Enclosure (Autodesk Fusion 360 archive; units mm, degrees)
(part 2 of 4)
sketch "Sketch32" plane through (0, -174.4464, 63.4933) normal (0, -0.9397, 0.342) x axis (1, 0, 0)
  line L1 (50, 6.0998) -> (50, -13.9002)
  line L2 (-45, 11.0998) -> (45, 11.0998)
  line L3 (-50, -13.9002) -> (-50, 6.0998)
  line L4 (45, -18.9002) -> (-45, -18.9002)
  line L5 (-48, -13.9002) -> (-48, 6.0998)
  line L6 (45, -16.9002) -> (-45, -16.9002)
  line L7 (48, 6.0998) -> (48, -13.9002)
  line L8 (-45, 9.0998) -> (45, 9.0998)
  line L9 (-46.5, -13.9002) -> (-46.5, 6.0998)
  line L10 (45, -15.4002) -> (-45, -15.4002)
  line L11 (46.5, 6.0998) -> (46.5, -13.9002)
  line L12 (-45, 7.5998) -> (45, 7.5998)
  line L13 (48, 9.0998) -> (-48, 9.0998)
  line L14 (48, -16.9002) -> (48, 9.0998)
  line L15 (-48, -16.9002) -> (48, -16.9002)
  line L16 (-48, 9.0998) -> (-48, -16.9002)
  line L17 (16, 9.0998) -> (-48, 9.0998)
  line L18 (16, -15.4002) -> (16, 9.0998)
  line L19 (-48, -15.4002) -> (16, -15.4002)
  line L20 (-48, 9.0998) -> (-48, -15.4002)
  line L21 (16, -15.4002) -> (-48, 9.0998)
  line L22 (-28, 3.8498) -> (-4, 3.8498)
  line L23 (-28, -10.1502) -> (-28, 3.8498)
  line L24 (-4, -10.1502) -> (-28, -10.1502)
  line L25 (-4, 3.8498) -> (-4, -10.1502)
  line L26 (-28, -10.1502) -> (-4, 3.8498)
  line L27 (-4, -10.1502) -> (-28, 3.8498)
  line L28 (16, -3.9002) -> (46.5, -3.9002)
  line L29 (47, 2.5998) -> (47, 8.0998)
  line L30 (45, 2.5998) -> (47, 2.5998)
  line L31 (41.5, 8.0998) -> (41.5, 6.0998)
  line L32 (47, 8.0998) -> (41.5, 8.0998)
  line L33 (41.5, -13.9002) -> (41.5, -15.9002)
  line L34 (47, -10.4002) -> (45, -10.4002)
  line L35 (47, -15.9002) -> (47, -10.4002)
  line L36 (41.5, -15.9002) -> (47, -15.9002)
  line L37 (-41.5, 6.0998) -> (-41.5, 8.0998)
  line L38 (-47, 2.5998) -> (-45, 2.5998)
  line L39 (-47, 8.0998) -> (-47, 2.5998)
  line L40 (-41.5, 8.0998) -> (-47, 8.0998)
  line L41 (-45, -10.4002) -> (-47, -10.4002)
  line L42 (-41.5, -15.9002) -> (-41.5, -13.9002)
  line L43 (-47, -15.9002) -> (-41.5, -15.9002)
  line L44 (-47, -10.4002) -> (-47, -15.9002)
  line L45 (16, -16.9002) -> (16, 9.0998)
  arc A1 centre (45, -13.9002) radius 5 clockwise from (50, -13.9002) to (45, -18.9002)
  arc A2 centre (45, 6.0998) radius 5 clockwise from (45, 11.0998) to (50, 6.0998)
  arc A3 centre (-45, 6.0998) radius 5
  arc A4 centre (-45, -13.9002) radius 5 clockwise from (-45, -18.9002) to (-50, -13.9002)
  circle C1 centre (31.25, -3.9002) radius 10
  arc A5 centre (-45, -13.9002) radius 3 clockwise from (-45, -16.9002) to (-48, -13.9002)
  arc A6 centre (45, -13.9002) radius 3 clockwise from (48, -13.9002) to (45, -16.9002)
  arc A7 centre (45, 6.0998) radius 3 clockwise from (45, 9.0998) to (48, 6.0998)
  arc A8 centre (-45, 6.0998) radius 3 clockwise from (-48, 6.0998) to (-45, 9.0998)
  arc A9 centre (-45, -13.9002) radius 1.5 clockwise from (-45, -15.4002) to (-46.5, -13.9002)
  arc A10 centre (45, -13.9002) radius 1.5 clockwise from (46.5, -13.9002) to (45, -15.4002)
  arc A11 centre (45, 6.0998) radius 1.5 clockwise from (45, 7.5998) to (46.5, 6.0998)
  arc A12 centre (-45, 6.0998) radius 1.5 clockwise from (-46.5, 6.0998) to (-45, 7.5998)
  arc A13 centre (45, 6.0998) radius 3.5 clockwise from (45, 2.5998) to (41.5, 6.0998)
  arc A14 centre (45, -13.9002) radius 3.5 clockwise from (41.5, -13.9002) to (45, -10.4002)
  arc A15 centre (-45, 6.0998) radius 3.5 clockwise from (-41.5, 6.0998) to (-45, 2.5998)
  arc A16 centre (-45, -13.9002) radius 3.5 clockwise from (-45, -10.4002) to (-41.5, -13.9002)
  point P44 (16, -15.4002)
  point P50 (-16, -3.1502)
  point P51 (46.5, -3.9002)
  point P52 (16, -3.9002)
  point P14 (31.25, -3.9002)
  point P77 (16, -16.9002)
  point P39 (-48, 9.0998)
  point P40 (48, 9.0998)
  point P48 (-28, -10.1502)
  point P49 (-4, -10.1502)
  point P47 (-28, 3.8498)
  horizontal L13
  vertical L14
  horizontal L15
  vertical L16
  collinear L8 L13
  collinear L7 L14
  collinear L6 L15
  collinear L5 L16
  horizontal L17
  vertical L18
  horizontal L19
  vertical L20
  coincident L10 P44
  horizontal L22
  perpendicular L22 L23
  parallel L22 L24
  parallel L23 L25
  coincident L26 P50
  coincident L27 P50
  midpoint L21 P50
  midpoint L11 P51
  coincident L18 P52
  perpendicular L18 L28
  midpoint P14 L28
  vertical L45
  coincident L15 P77
  dimension "d199" diameter C1 = 20
  dimension "d200" = -2
  dimension "d201" = -1.5
  dimension "d202" distance P39 P40 = 96
  dimension "d203" distance L16 L18 = 64 (= "( d202 * 2 ) / 3")
  dimension "d204" distance P48 P49 = 24
  dimension "d205" distance P47 P48 = 14
extrude "Extrude23" cut sketch "Sketch32" profile of C1 L9 L10 L12 L22 L23 L24 L25 L37 A15 L38 L41 A16 L42 L45 against normal blind 15
extrude "Extrude24" add sketch "Sketch32" profile of L8 A6 L5 A5 L6 L7 A7 A8 A12 L9 A9 L11 A10 L10 A11 L12 L29 L30 L31 L32 L33 L34 L35 L36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 against normal blind 13
extrude "Extrude25" cut sketch "Sketch32" profile of L8 L5 A5 L6 A8 A12 L9 A9 L10 L12 L37 A15 L38 L39 L40 L41 A16 L42 L43 L44 L45 no distance stored
sketch "Sketch33" plane through (0, -130, 0) normal (0, 1, 0) x axis (-1, 0, 0)
  line L1 (-35, 45.945) -> (35, 45.945)
  line L2 (35, 54.945) -> (-35, 54.945)
  line L3 (35, 42.945) -> (-35, 42.945)
  line L4 (-35, 57.945) -> (35, 57.945)
  arc A1 centre (-35, 50.445) radius 4.5 clockwise from (-35, 45.945) to (-35, 54.945)
  arc A2 centre (35, 50.445) radius 4.5 clockwise from (35, 54.945) to (35, 45.945)
  arc A3 centre (-35, 50.445) radius 7.5 clockwise from (-35, 42.945) to (-35, 57.945)
  arc A4 centre (35, 50.445) radius 7.5 clockwise from (35, 57.945) to (35, 42.945)
extrude "Extrude26" cut sketch "Sketch33" profile of L1 A1 L2 A2 against normal blind 25
sketch "Sketch34" plane through (0, -174.4464, 63.4933) normal (0, -0.9397, 0.342) x axis (1, 0, 0)
  line L1 (16, -16.9002) -> (16, 9.0998)
  line L2 (-45, -16.9002) -> (16, -16.9002)
  line L3 (-48, 6.0998) -> (-48, -13.9002)
  line L4 (16, 9.0998) -> (-45, 9.0998)
  line L5 (50, 6.0998) -> (50, -13.9002)
  line L6 (-45, 11.0998) -> (45, 11.0998)
  line L7 (-50, -13.9002) -> (-50, 6.0998)
  line L8 (45, -18.9002) -> (-45, -18.9002)
  line L9 (45, -18.9002) -> (-45, -18.9002)
  line L10 (50, 6.0998) -> (50, -13.9002)
  line L11 (-45, 11.0998) -> (45, 11.0998)
  line L12 (-50, -13.9002) -> (-50, 6.0998)
  line L13 (-4, -10.1502) -> (-28, 3.8498)
  line L14 (-28, -10.1502) -> (-4, 3.8498)
  line L15 (16, -3.9002) -> (46.5, -3.9002)
  line L16 (31.25, -15) -> (31.25, 6.0998)
  arc A1 centre (-45, -13.9002) radius 3 clockwise from (-45, -16.9002) to (-48, -13.9002)
  arc A2 centre (-45, 6.0998) radius 3 clockwise from (-48, 6.0998) to (-45, 9.0998)
  arc A3 centre (45, -13.9002) radius 5 clockwise from (50, -13.9002) to (45, -18.9002)
  arc A4 centre (45, 6.0998) radius 5 clockwise from (45, 11.0998) to (50, 6.0998)
  arc A5 centre (-45, 6.0998) radius 5 clockwise from (-50, 6.0998) to (-45, 11.0998)
  arc A6 centre (-45, -13.9002) radius 5 clockwise from (-45, -18.9002) to (-50, -13.9002)
  circle C1 centre (31.25, -3.9002) radius 10
  arc A7 centre (-45, -13.9002) radius 5 clockwise from (-45, -18.9002) to (-50, -13.9002)
  arc A8 centre (45, -13.9002) radius 5 clockwise from (50, -13.9002) to (45, -18.9002)
  arc A9 centre (45, 6.0998) radius 5 clockwise from (45, 11.0998) to (50, 6.0998)
  arc A10 centre (-45, 6.0998) radius 5 clockwise from (-50, 6.0998) to (-45, 11.0998)
  point P41 (31.25, 6.0998)
  coincident C1 P41
sketch "Sketch36" plane through (0, -160.351, 58.363) normal (0, -0.9397, 0.342) x axis (1, 0, 0)
  line L1 (45, -18.9002) -> (-45, -18.9002)
  line L2 (50, 6.0998) -> (50, -13.9002)
  line L3 (-45, 11.0998) -> (45, 11.0998)
  line L4 (-50, -13.9002) -> (-50, 6.0998)
  line L5 (0, -18.9002) -> (0, 11.0998)
  line L6 (-47, 8.0998) -> (47, 8.0998)
  line L7 (-47, -15.9002) -> (-47, 8.0998)
  line L8 (47, -15.9002) -> (-47, -15.9002)
  line L9 (47, 8.0998) -> (47, -15.9002)
  line L10 (-47, -15.9002) -> (47, 8.0998)
  line L11 (47, -15.9002) -> (-47, 8.0998)
  arc A1 centre (-45, -13.9002) radius 5 clockwise from (-45, -18.9002) to (-50, -13.9002)
  arc A2 centre (45, -13.9002) radius 5 clockwise from (50, -13.9002) to (45, -18.9002)
  arc A3 centre (45, 6.0998) radius 5 clockwise from (45, 11.0998) to (50, 6.0998)
  arc A4 centre (-45, 6.0998) radius 5 clockwise from (-50, 6.0998) to (-45, 11.0998)
  point P14 (0, 11.0998)
  point P15 (0, -18.9002)
  point P20 (0, -3.9002)
  point P18 (-47, -15.9002)
  point P19 (47, -15.9002)
  point P17 (-47, 8.0998)
  midpoint L3 P14
  midpoint L1 P15
  horizontal L6
  perpendicular L6 L7
  parallel L6 L8
  parallel L7 L9
  coincident L10 P20
  coincident L11 P20
  midpoint L5 P20
  dimension "d229" distance P18 P19 = 94
  dimension "d230" distance P17 P18 = 24
extrude "Extrude27" cut sketch "Sketch36" profile of L6 L7 L8 L9 against normal blind 10
sketch "Sketch37" plane through (0, -162.2304, 59.047) normal (0, 0.9397, -0.342) x axis (-1, 0, 0)
  line L1 (-47, -15.9002) -> (-47, 8.0998)
  line L2 (47, -15.9002) -> (-47, -15.9002)
  line L3 (47, 8.0998) -> (47, -15.9002)
  line L4 (-47, 8.0998) -> (47, 8.0998)
  line L5 (-46.5, 2.5998) -> (-46.5, -10.4002)
  line L6 (-45, 2.5998) -> (-46.5, 2.5998)
  line L7 (-41.5, 7.5998) -> (-41.5, 6.0998)
  line L8 (41.5, 7.5998) -> (-41.5, 7.5998)
  line L9 (41.5, 6.0998) -> (41.5, 7.5998)
  line L10 (46.5, 2.5998) -> (45, 2.5998)
  line L11 (46.5, -10.4002) -> (46.5, 2.5998)
  line L12 (45, -10.4002) -> (46.5, -10.4002)
  line L13 (41.5, -15.4002) -> (41.5, -13.9002)
  line L14 (-41.5, -15.4002) -> (41.5, -15.4002)
  line L15 (-41.5, -13.9002) -> (-41.5, -15.4002)
  line L16 (-46.5, -10.4002) -> (-45, -10.4002)
  arc A1 centre (-45, 6.0998) radius 3.5 clockwise from (-41.5, 6.0998) to (-45, 2.5998)
  arc A2 centre (45, 6.0998) radius 3.5 clockwise from (45, 2.5998) to (41.5, 6.0998)
  arc A3 centre (45, -13.9002) radius 3.5 clockwise from (41.5, -13.9002) to (45, -10.4002)
  arc A4 centre (-45, -13.9002) radius 3.5 clockwise from (-45, -10.4002) to (-41.5, -13.9002)
  circle C1 centre (-45, 6.0998) radius 1.5
  circle C2 centre (-45, -13.9002) radius 1.5
  circle C3 centre (45, -13.9002) radius 1.5
  circle C4 centre (45, 6.0998) radius 1.5
extrude "Extrude28" cut sketch "Sketch37" profile of C1 C2 C3 C4 against normal blind 11
sketch "Sketch39" plane through (0, -150.9541, 54.9428) normal (0, -0.9397, 0.342) x axis (1, 0, 0)
  line L1 (47, 8.0998) -> (47, -15.9002)
  line L2 (-47, 8.0998) -> (47, 8.0998)
  line L3 (-47, -15.9002) -> (-47, 8.0998)
  line L4 (47, -15.9002) -> (-47, -15.9002)
  line L5 (-35, -9.5752) -> (35, -9.5752)
  line L6 (35, 0.0024) -> (-35, 0.0024)
  line L7 (46.5, 2.5998) -> (46.5, -10.4002)
  line L8 (45, 2.5998) -> (46.5, 2.5998)
  line L9 (41.5, 7.5998) -> (41.5, 6.0998)
  line L10 (-41.5, 7.5998) -> (41.5, 7.5998)
  line L11 (-41.5, 6.0998) -> (-41.5, 7.5998)
  line L12 (-46.5, 2.5998) -> (-45, 2.5998)
  line L13 (-46.5, -10.4002) -> (-46.5, 2.5998)
  line L14 (-45, -10.4002) -> (-46.5, -10.4002)
  line L15 (-41.5, -15.4002) -> (-41.5, -13.9002)
  line L16 (41.5, -15.4002) -> (-41.5, -15.4002)
  line L17 (41.5, -13.9002) -> (41.5, -15.4002)
  line L18 (46.5, -10.4002) -> (45, -10.4002)
  line L19 (47, -15.9002) -> (47, 8.0998)
  line L20 (-47, -15.9002) -> (47, -15.9002)
  line L21 (-47, 8.0998) -> (-47, -15.9002)
  line L22 (47, 8.0998) -> (-47, 8.0998)
  closed curve K1 centre (35, -4.7864)
  closed curve K2 centre (-35, -4.7864)
  circle C1 centre (-45, 6.0998) radius 1.5
  circle C2 centre (45, 6.0998) radius 1.5
  circle C3 centre (-45, -13.9002) radius 1.5
  circle C4 centre (45, -13.9002) radius 1.5
  arc A1 centre (45, 6.0998) radius 3.5 clockwise from (45, 2.5998) to (41.5, 6.0998)
  arc A2 centre (-45, 6.0998) radius 3.5 clockwise from (-41.5, 6.0998) to (-45, 2.5998)
  arc A3 centre (-45, -13.9002) radius 3.5 clockwise from (-45, -10.4002) to (-41.5, -13.9002)
  arc A4 centre (45, -13.9002) radius 3.5 clockwise from (41.5, -13.9002) to (45, -10.4002)
  circle C5 centre (-45, -13.9002) radius 1.5
  circle C6 centre (45, 6.0998) radius 1.5
  circle C7 centre (-45, 6.0998) radius 1.5
  circle C8 centre (45, -13.9002) radius 1.5
extrude "Extrude30" add sketch "Sketch39" profile of L1 L2 L3 L4 C1 C2 C3 C4 L7 L8 A1 L9 L10 L11 A2 L12 L13 L14 A3 L15 L16 L17 A4 L18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 along normal blind 10
sketch "Sketch38" plane through (0, -146.2556, 53.2327) normal (0, 0.9397, -0.342) x axis (-1, 0, 0)
  line L1 (-35, -10.9479) -> (35, -10.9479)
  line L2 (35, 5.0147) -> (-35, 5.0147)
  line L3 (45, -18.9002) -> (-45, -18.9002)
  line L4 (50, 6.0998) -> (50, -13.9002)
  line L5 (-45, 11.0998) -> (45, 11.0998)
  line L6 (-50, -13.9002) -> (-50, 6.0998)
  closed curve K1 centre (-35, -2.9666)
  closed curve K2 centre (35, -2.9666)
  arc A1 centre (-45, -13.9002) radius 5 clockwise from (-45, -18.9002) to (-50, -13.9002)
  arc A2 centre (45, -13.9002) radius 5 clockwise from (50, -13.9002) to (45, -18.9002)
  arc A3 centre (45, 6.0998) radius 5 clockwise from (45, 11.0998) to (50, 6.0998)
  arc A4 centre (-45, 6.0998) radius 5 clockwise from (-50, 6.0998) to (-45, 11.0998)
  circle C1 centre (45, 6.0998) radius 1.5
  circle C2 centre (-45, 6.0998) radius 1.5
  circle C3 centre (45, -13.9002) radius 1.5
  circle C4 centre (-45, -13.9002) radius 1.5
  circle C5 centre (-45, 6.0998) radius 3
  circle C6 centre (-45, -13.9002) radius 3
  circle C7 centre (45, 6.0998) radius 3
  circle C8 centre (45, -13.9002) radius 3
  concentric A4 C5
  concentric A1 C6
  concentric A3 C7
  concentric A2 C8
  dimension "d235" diameter C5 = 6
  dimension "d236" diameter C6 = 6
  dimension "d237" diameter C7 = 6
  dimension "d238" diameter C8 = 6
extrude "Extrude29" cut sketch "Sketch38" profile of C1 C2 C3 C4 C5 C6 C7 C8 against normal blind 9
sketch "Sketch40" plane through (0, -172.567, 62.8092) normal (0, -0.9397, 0.342) x axis (1, 0, 0)
  line L1 (-48, -13.9002) -> (-48, 6.0998)
  line L2 (16, -16.9002) -> (-45, -16.9002)
  line L3 (16, -15.4002) -> (16, -16.9002)
  line L4 (-41.5, -15.4002) -> (16, -15.4002)
  line L5 (-41.5, -13.9002) -> (-41.5, -15.4002)
  line L6 (-46.5, -10.4002) -> (-45, -10.4002)
  line L7 (-46.5, 2.5998) -> (-46.5, -10.4002)
  line L8 (-45, 2.5998) -> (-46.5, 2.5998)
  line L9 (-41.5, 7.5998) -> (-41.5, 6.0998)
  line L10 (16, 7.5998) -> (-41.5, 7.5998)
  line L11 (16, 9.0998) -> (16, 7.5998)
  line L12 (-45, 9.0998) -> (16, 9.0998)
  line L13 (41.5, -15.4002) -> (-41.5, -15.4002)
  line L14 (41.5, -13.9002) -> (41.5, -15.4002)
  line L15 (46.5, -10.4002) -> (45, -10.4002)
  line L16 (46.5, 2.5998) -> (46.5, -10.4002)
  line L17 (45, 2.5998) -> (46.5, 2.5998)
  line L18 (41.5, 7.5998) -> (41.5, 6.0998)
  line L19 (-41.5, 7.5998) -> (41.5, 7.5998)
  line L20 (-41.5, 6.0998) -> (-41.5, 7.5998)
  line L21 (-46.5, 2.5998) -> (-45, 2.5998)
  line L22 (-46.5, -10.4002) -> (-46.5, 2.5998)
  line L23 (-45, -10.4002) -> (-46.5, -10.4002)
  line L24 (-41.5, -15.4002) -> (-41.5, -13.9002)
  line L25 (-35, -9.5752) -> (35, -9.5752)
  line L26 (35, 0.0024) -> (-35, 0.0024)
  line L27 (16, -16.9002) -> (16, 9.0998)
  circle C1 centre (-45, 6.0998) radius 1.5
  circle C2 centre (-45, -13.9002) radius 1.5
  arc A1 centre (-45, 6.0998) radius 3 clockwise from (-48, 6.0998) to (-45, 9.0998)
  arc A2 centre (-45, -13.9002) radius 3 clockwise from (-45, -16.9002) to (-48, -13.9002)
  arc A3 centre (-45, -13.9002) radius 3.5 clockwise from (-45, -10.4002) to (-41.5, -13.9002)
  arc A4 centre (-45, 6.0998) radius 3.5 clockwise from (-41.5, 6.0998) to (-45, 2.5998)
  arc A5 centre (45, -13.9002) radius 3.5 clockwise from (41.5, -13.9002) to (45, -10.4002)
  arc A6 centre (45, 6.0998) radius 3.5 clockwise from (45, 2.5998) to (41.5, 6.0998)
  arc A7 centre (-45, 6.0998) radius 3.5 clockwise from (-41.5, 6.0998) to (-45, 2.5998)
  arc A8 centre (-45, -13.9002) radius 3.5 clockwise from (-45, -10.4002) to (-41.5, -13.9002)
  closed curve K1 centre (35, -4.7864)
  closed curve K2 centre (-35, -4.7864)
extrude "Extrude31" new body sketch "Sketch40" profile of C1 C2 A1 L1 A2 L2 L3 L4 L5 A3 L6 L7 L8 A4 L9 L10 L11 L12 L13 L19 L20 A7 L21 L22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 along normal blind 2 (= "acrylic")
extrude "Extrude32" add of existing geometry blind 11.21
extrude "Extrude33" add of existing geometry blind 2
sketch "Sketch43" plane through (0, -116.79, 0) normal (0, 1, 0) x axis (-1, 0, 0)
  line L1 (-35, 45.945) -> (35, 45.945)
  line L2 (35, 54.945) -> (-35, 54.945)
  line L3 (35, 42.945) -> (-35, 42.945)
  line L4 (-35, 57.945) -> (35, 57.945)
  line L5 (35, 37.945) -> (-35, 37.945)
  line L6 (-35, 62.945) -> (35, 62.945)
  arc A1 centre (-35, 50.445) radius 4.5 clockwise from (-35, 45.945) to (-35, 54.945)
  arc A2 centre (35, 50.445) radius 4.5 clockwise from (35, 54.945) to (35, 45.945)
  arc A3 centre (-35, 50.445) radius 7.5 clockwise from (-35, 42.945) to (-35, 57.945)
  arc A4 centre (35, 50.445) radius 7.5 clockwise from (35, 57.945) to (35, 42.945)
  arc A5 centre (35, 50.445) radius 12.5 clockwise from (35, 62.945) to (35, 37.945)
  arc A6 centre (-35, 50.445) radius 12.5 clockwise from (-35, 37.945) to (-35, 62.945)
  dimension "d249" = 5
extrude "Extrude34" add sketch "Sketch43" profile of A3 L3 A4 L4 L5 L6 A5 A6 against normal blind 2
extrude "Extrude35" add of existing geometry blind 3
sketch "Sketch44" plane through (0, -113.79, 0) normal (0, 1, 0) x axis (-1, 0, 0)
  line L1 (35, 37.945) -> (-35, 37.945)
  line L2 (-35, 62.945) -> (35, 62.945)
  line L3 (-35, 45.945) -> (35, 45.945)
  line L4 (35, 54.945) -> (-35, 54.945)
  line L5 (-39.5, 50.445) -> (-47.5, 50.445)
  line L6 (47.5, 50.445) -> (39.5, 50.445)
  line L7 (0, 37.945) -> (0, 62.945)
  arc A1 centre (-35, 50.445) radius 12.5 clockwise from (-35, 37.945) to (-35, 62.945)
  arc A2 centre (35, 50.445) radius 12.5 clockwise from (35, 62.945) to (35, 37.945)
  arc A3 centre (-35, 50.445) radius 4.5 clockwise from (-35, 45.945) to (-35, 54.945)
  arc A4 centre (35, 50.445) radius 4.5 clockwise from (35, 54.945) to (35, 45.945)
  circle C1 centre (-44.8333, 50.445) radius 1.5
  circle C2 centre (44.8333, 50.445) radius 1.5
  point P12 (-47.5, 50.445)
  point P13 (-39.5, 50.445)
  point P14 (39.5, 50.445)
  point P15 (47.5, 50.445)
  point P16 (-44.8333, 50.445)
  point P17 (0, 62.945)
  point P18 (0, 37.945)
  midpoint A1 P12
  midpoint A3 P13
  midpoint A4 P14
  midpoint A2 P15
  coincident L5 P16
  midpoint L2 P17
  midpoint L1 P18
  symmetric C1 L7 C2
  dimension "d254" distance P12 P13 = 8
  dimension "d255" diameter C1 = 3
  dimension "d256" distance P13 P16 = 5.3333 (= "( d254 * 2 ) / 3")
extrude "Extrude36" cut sketch "Sketch44" profile of C1 C2 against normal blind 5
work_plane "WorkPlane5"
split "Split2" bodies "CASE_FEED"
offset_faces "OffsetFaces2" distance 2
sketch "Sketch45" plane through (0, -146.2556, 53.2327) normal (0, -0.9397, 0.342) x axis (1, 0, 0)
  line L1 (-35, 5.0147) -> (35, 5.0147)
  line L2 (35, -10.9479) -> (-35, -10.9479)
  line L3 (35, -0.3061) -> (-35, -0.3061)
  line L4 (-35, -5.627) -> (35, -5.627)
  line L5 (-42.5, -2.9666) -> (-37.5, -2.9666)
  line L6 (42.5, -2.9666) -> (37.5, -2.9666)
  line L7 (35, -2.9666) -> (-35, -2.9666)
  closed curve K1 centre (35, -2.9666)
  closed curve K2 centre (-35, -2.9666)
  closed curve K3 centre (-35, -2.9666)
  closed curve K4 centre (35, -2.9666)
  circle C1 centre (-40, -2.9666) radius 1.25
  circle C2 centre (40, -2.9666) radius 1.25
  point P12 (-37.5, -2.9666)
  point P13 (-42.5, -2.9666)
  point P14 (37.5, -2.9666)
  point P15 (42.5, -2.9666)
  point P7 (-35, -2.9666)
  point P16 (-35, -2.9666)
  point P4 (35, -2.9666)
  point P17 (35, -2.9666)
  point P18 (-40, -2.9666)
  point P19 (40, -2.9666)
  coincident K3 P12
  coincident K2 P13
  parallel L3 L5
  coincident K4 P14
  coincident K1 P15
  horizontal L6
  coincident P7 P16
  coincident P4 P17
  collinear L5 L7
  collinear L6 L7
  midpoint L5 P18
  midpoint L6 P19
  dimension "d260" diameter C1 = 2.5
  dimension "d261" diameter C2 = 2.5
offset_faces "OffsetFaces3" distance 2
extrude "Extrude37" cut sketch "Sketch45" profile of C1 C2 along normal blind 5 and against normal blind 3
sketch "Sketch46" plane through (0, -130, 0) normal (0, -1, 0) x axis (1, 0, 0)
  line L1 (-64.79, 23.18) -> (-64.79, 72.18)
  line L2 (-121.29, 15.68) -> (-72.29, 15.68)
  line L3 (-128.79, 72.18) -> (-128.79, 23.18)
  line L4 (-72.29, 79.68) -> (-121.29, 79.68)
  line L5 (35, 57.945) -> (-35, 57.945)
  line L6 (-35, 42.945) -> (35, 42.945)
  line L7 (72.29, 15.68) -> (121.29, 15.68)
  line L8 (64.79, 72.18) -> (64.79, 23.18)
  line L9 (121.29, 79.68) -> (72.29, 79.68)
  line L10 (128.79, 23.18) -> (128.79, 72.18)
  line L11 (148.79, 11.21) -> (-148.79, 11.21)
  line L12 (148.79, 89.68) -> (148.79, 11.21)
  line L13 (-148.79, 89.68) -> (148.79, 89.68)
  line L14 (-148.79, 11.21) -> (-148.79, 89.68)
  arc A1 centre (-72.29, 23.18) radius 7.5 clockwise from (-64.79, 23.18) to (-72.29, 15.68)
  arc A2 centre (-121.29, 23.18) radius 7.5 clockwise from (-121.29, 15.68) to (-128.79, 23.18)
  arc A3 centre (-121.29, 72.18) radius 7.5 clockwise from (-128.79, 72.18) to (-121.29, 79.68)
  arc A4 centre (-72.29, 72.18) radius 7.5 clockwise from (-72.29, 79.68) to (-64.79, 72.18)
  arc A5 centre (-35, 50.445) radius 7.5 clockwise from (-35, 42.945) to (-35, 57.945)
  arc A6 centre (35, 50.445) radius 7.5 clockwise from (35, 57.945) to (35, 42.945)
  arc A7 centre (72.29, 23.18) radius 7.5 clockwise from (72.29, 15.68) to (64.79, 23.18)
  arc A8 centre (72.29, 72.18) radius 7.5 clockwise from (64.79, 72.18) to (72.29, 79.68)
  arc A9 centre (121.29, 72.18) radius 7.5 clockwise from (121.29, 79.68) to (128.79, 72.18)
  arc A10 centre (121.29, 23.18) radius 7.5 clockwise from (128.79, 23.18) to (121.29, 15.68)
component_from_bodies "Body->Comp1"
component_from_bodies "Body->Comp2"
component_from_bodies "Body->Comp3"
component_from_bodies "Body->Comp4"
component_from_bodies "Body->Comp5"
component_from_bodies "Body->Comp6"
component_from_bodies "Body->Comp7"
component_from_bodies "Body->Comp8"
component_from_bodies "Body->Comp9"
component_from_bodies "Body->Comp10"
component_from_bodies "Body->Comp11"
component_from_bodies "Body->Comp12"
component_from_bodies "Body->Comp13"
component_from_bodies "Body->Comp14"
component_from_bodies "Body->Comp15"
component_from_bodies "Body->Comp16"
component_from_bodies "Body->Comp17"
component_from_bodies "Body->Comp18"
component_from_bodies "Body->Comp19"
component_from_bodies "Body->Comp20"
component_from_bodies "Body->Comp21"
canvas "Canvas2"
sketch "Sketch26" plane through (0, 0, 0) normal (0, 0, 1) x axis (1, 0, 0)
  line L1 (243.58, 140.44) -> (243.58, 189.44)
  line L2 (300.08, 132.94) -> (251.08, 132.94)
  line L3 (307.58, 189.44) -> (307.58, 140.44)
  line L4 (251.08, 196.94) -> (300.08, 196.94)
  line L5 (143.79, 175.205) -> (213.79, 175.205)
  line L6 (213.79, 160.205) -> (143.79, 160.205)
  line L7 (106.5, 132.94) -> (57.5, 132.94)
  line L8 (114, 189.44) -> (114, 140.44)
  line L9 (57.5, 196.94) -> (106.5, 196.94)
  line L10 (50, 140.44) -> (50, 189.44)
  line L11 (30, 128.47) -> (327.58, 128.47)
  line L12 (30, 206.94) -> (30, 128.47)
  line L13 (327.58, 206.94) -> (30, 206.94)
  line L14 (327.58, 128.47) -> (327.58, 206.94)
  line L15 (120.29, 66.985) -> (120.29, 71.485)
  line L16 (222.54, 52.235) -> (135.04, 52.235)
  line L17 (237.29, 71.485) -> (237.29, 66.985)
  line L18 (135.04, 86.235) -> (222.54, 86.235)
  line L19 (30, 30) -> (327.58, 30)
  line L20 (30, 108.47) -> (30, 30)
  line L21 (327.58, 108.47) -> (30, 108.47)
  line L22 (327.58, 30) -> (327.58, 108.47)
  line L23 (300.08, 137.94) -> (251.08, 137.94)
  line L24 (248.58, 140.44) -> (248.58, 189.44)
  line L25 (300.08, 137.94) -> (251.08, 137.94)
  line L26 (302.58, 189.44) -> (302.58, 140.44)
  line L27 (251.08, 191.94) -> (300.08, 191.94)
  line L28 (251.08, 132.94) -> (300.08, 132.94)
  line L29 (243.58, 189.44) -> (243.58, 140.44)
  line L30 (300.08, 196.94) -> (251.08, 196.94)
  line L31 (307.58, 140.44) -> (307.58, 189.44)
  line L32 (55, 140.44) -> (55, 189.44)
  line L33 (106.5, 137.94) -> (57.5, 137.94)
  line L34 (109, 189.44) -> (109, 140.44)
  line L35 (57.5, 191.94) -> (106.5, 191.94)
  line L36 (114, 140.44) -> (114, 189.44)
  line L37 (57.5, 132.94) -> (106.5, 132.94)
  line L38 (50, 189.44) -> (50, 140.44)
  line L39 (106.5, 196.94) -> (57.5, 196.94)
  arc A1 centre (251.08, 140.44) radius 7.5 clockwise from (251.08, 132.94) to (243.58, 140.44)
  arc A2 centre (300.08, 140.44) radius 7.5 clockwise from (307.58, 140.44) to (300.08, 132.94)
  arc A3 centre (300.08, 189.44) radius 7.5 clockwise from (300.08, 196.94) to (307.58, 189.44)
  arc A4 centre (251.08, 189.44) radius 7.5 clockwise from (243.58, 189.44) to (251.08, 196.94)
  arc A5 centre (213.79, 167.705) radius 7.5 clockwise from (213.79, 175.205) to (213.79, 160.205)
  arc A6 centre (143.79, 167.705) radius 7.5 clockwise from (143.79, 160.205) to (143.79, 175.205)
  arc A7 centre (106.5, 140.44) radius 7.5 clockwise from (114, 140.44) to (106.5, 132.94)
  arc A8 centre (106.5, 189.44) radius 7.5 clockwise from (106.5, 196.94) to (114, 189.44)
  arc A9 centre (57.5, 189.44) radius 7.5 clockwise from (50, 189.44) to (57.5, 196.94)
  arc A10 centre (57.5, 140.44) radius 7.5 clockwise from (57.5, 132.94) to (50, 140.44)
  arc A11 centre (135.04, 71.485) radius 14.75 clockwise from (120.29, 71.485) to (135.04, 86.235)
  arc A12 centre (135.04, 66.985) radius 14.75 clockwise from (135.04, 52.235) to (120.29, 66.985)
  arc A13 centre (222.54, 66.985) radius 14.75 clockwise from (237.29, 66.985) to (222.54, 52.235)
  arc A14 centre (222.54, 71.485) radius 14.75 clockwise from (222.54, 86.235) to (237.29, 71.485)
  arc A15 centre (251.08, 189.44) radius 2.5 clockwise from (248.58, 189.44) to (251.08, 191.94)
  arc A16 centre (251.08, 140.44) radius 2.5 clockwise from (251.08, 137.94) to (248.58, 140.44)
  arc A17 centre (300.08, 140.44) radius 2.5 clockwise from (302.58, 140.44) to (300.08, 137.94)
  arc A18 centre (300.08, 189.44) radius 2.5 clockwise from (300.08, 191.94) to (302.58, 189.44)
  arc A19 centre (300.08, 140.44) radius 7.5 clockwise from (307.58, 140.44) to (300.08, 132.94)
  arc A20 centre (251.08, 140.44) radius 7.5 clockwise from (251.08, 132.94) to (243.58, 140.44)
  arc A21 centre (251.08, 189.44) radius 7.5 clockwise from (243.58, 189.44) to (251.08, 196.94)
  arc A22 centre (300.08, 189.44) radius 7.5 clockwise from (300.08, 196.94) to (307.58, 189.44)
  arc A23 centre (57.5, 189.44) radius 2.5 clockwise from (55, 189.44) to (57.5, 191.94)
  arc A24 centre (57.5, 140.44) radius 2.5 clockwise from (57.5, 137.94) to (55, 140.44)
  arc A25 centre (106.5, 140.44) radius 2.5 clockwise from (109, 140.44) to (106.5, 137.94)
  arc A26 centre (106.5, 189.44) radius 2.5 clockwise from (106.5, 191.94) to (109, 189.44)
  arc A27 centre (106.5, 189.44) radius 7.5 clockwise from (106.5, 196.94) to (114, 189.44)
  arc A28 centre (106.5, 140.44) radius 7.5 clockwise from (114, 140.44) to (106.5, 132.94)
  arc A29 centre (57.5, 140.44) radius 7.5 clockwise from (57.5, 132.94) to (50, 140.44)
  arc A30 centre (57.5, 189.44) radius 7.5 clockwise from (50, 189.44) to (57.5, 196.94)
sketch "Sketch27" plane through (0, 0, 0) normal (0, 0, 1) x axis (1, 0, 0)
  line L1 (-95, 0) -> (0, 0)
  line L2 (-95, 400) -> (-95, 0)
  line L3 (0, 400) -> (-95, 400)
  line L4 (0, 0) -> (0, 400)
  point P2 (0, 0)
  point P3 (-95, 0)
  point P5 (0, 400)
  horizontal L1
  vertical L2
  horizontal L3
  vertical L4
  dimension "d174" distance P2 P3 = 95
  dimension "d175" distance P2 P5 = 400
base_feature "Base Feature3" bodies "dogboneTool (1)"
combine "Combine2" bodies "dogboneTool (1)"
base_feature "Base Feature2" bodies "dogboneTool"
combine "Combine1" bodies "dogboneTool"
sketch "Sketch28" plane through (0, 0, 0) normal (0, 0, 1) x axis (1, 0, 0)
  line L1 (-37.6482, 51.9729) -> (-26.4382, 51.9729)
  line L2 (-37.6482, 58.9403) -> (-37.6482, 51.9729)
  line L3 (-52.6482, 63.1829) -> (-41.8908, 63.1829)
  line L4 (-52.6482, 73.1829) -> (-52.6482, 63.1829)
  line L5 (-37.6482, 73.1829) -> (-52.6482, 73.1829)
  line L6 (-22.6482, 275.7629) -> (-22.6482, 88.1829)
  line L7 (-52.6482, 290.7629) -> (-37.6482, 290.7629)
  line L8 (-52.6482, 300.7629) -> (-52.6482, 290.7629)
  line L9 (-41.8908, 300.7629) -> (-52.6482, 300.7629)
  line L10 (-37.6482, 311.9729) -> (-37.6482, 305.0056)
  line L11 (-26.4382, 311.9729) -> (-37.6482, 311.9729)
  line L12 (-11.4382, 66.9729) -> (-11.4382, 296.9729)
  line L13 (-85, 255) -> (-85, 25)
  line L14 (-58.79, 270) -> (-70, 270)
  line L15 (-58.79, 263.0326) -> (-58.79, 270)
  line L16 (-43.79, 258.79) -> (-54.5473, 258.79)
  line L17 (-43.79, 248.79) -> (-43.79, 258.79)
  line L18 (-58.79, 248.79) -> (-43.79, 248.79)
  line L19 (-73.79, 46.21) -> (-73.79, 233.79)
  line L20 (-43.79, 31.21) -> (-58.79, 31.21)
  line L21 (-43.79, 21.21) -> (-43.79, 31.21)
  line L22 (-54.5473, 21.21) -> (-43.79, 21.21)
  line L23 (-58.79, 10) -> (-58.79, 16.9674)
  line L24 (-70, 10) -> (-58.79, 10)
  line L25 (0, 400) -> (-95, 400)
  line L26 (-95, 400) -> (-95, 0)
  line L27 (0, 0) -> (0, 400)
  line L28 (-95, 0) -> (0, 0)
  arc A1 centre (-26.4382, 66.9729) radius 15 clockwise from (-11.4382, 66.9729) to (-26.4382, 51.9729)
  arc A2 centre (-37.6482, 88.1829) radius 15 clockwise from (-22.6482, 88.1829) to (-37.6482, 73.1829)
  arc A3 centre (-37.6482, 275.7629) radius 15 clockwise from (-37.6482, 290.7629) to (-22.6482, 275.7629)
  arc A4 centre (-26.4382, 296.9729) radius 15 clockwise from (-26.4382, 311.9729) to (-11.4382, 296.9729)
  arc A5 centre (-70, 25) radius 15 clockwise from (-70, 10) to (-85, 25)
  arc A6 centre (-70, 255) radius 15 clockwise from (-85, 255) to (-70, 270)
  arc A7 centre (-58.79, 233.79) radius 15 clockwise from (-73.79, 233.79) to (-58.79, 248.79)
  arc A8 centre (-58.79, 46.21) radius 15 clockwise from (-58.79, 31.21) to (-73.79, 46.21)
  arc A9 centre (-39.7695, 302.8843) radius 3 clockwise from (-37.6482, 305.0056) to (-41.8908, 300.7629)
  arc A10 centre (-39.7695, 61.0616) radius 3 clockwise from (-41.8908, 63.1829) to (-37.6482, 58.9403)
  arc A11 centre (-56.6687, 19.0887) radius 3 clockwise from (-58.79, 16.9674) to (-54.5473, 21.21)
  arc A12 centre (-56.6687, 260.9113) radius 3 clockwise from (-54.5473, 258.79) to (-58.79, 263.0326)
sketch "Sketch29" plane through (0, -174.4464, 63.4933) normal (0, -0.9397, 0.342) x axis (1, 0, 0)
  line L1 (50, 6.0998) -> (50, -13.9002)
  line L2 (-45, 11.0998) -> (45, 11.0998)
  line L3 (-50, -13.9002) -> (-50, 6.0998)
  line L4 (45, -18.9002) -> (-45, -18.9002)
  line L5 (1.9324, -10.0491) -> (-22.0676, -10.0491)
  line L6 (1.9324, 3.9509) -> (1.9324, -10.0491)
  line L7 (-22.0676, 3.9509) -> (1.9324, 3.9509)
  line L8 (-22.0676, -10.0491) -> (-22.0676, 3.9509)
  line L9 (16, -16.9002) -> (16, 9.0998)
  line L10 (-45, -16.9002) -> (16, -16.9002)
  line L11 (-48, 6.0998) -> (-48, -13.9002)
  line L12 (16, 9.0998) -> (-45, 9.0998)
  arc A1 centre (45, -13.9002) radius 5 clockwise from (50, -13.9002) to (45, -18.9002)
  arc A2 centre (45, 6.0998) radius 5 clockwise from (45, 11.0998) to (50, 6.0998)
  arc A3 centre (-45, 6.0998) radius 5 clockwise from (-50, 6.0998) to (-45, 11.0998)
  arc A4 centre (-45, -13.9002) radius 5 clockwise from (-45, -18.9002) to (-50, -13.9002)
  circle C1 centre (28.9365, -2.8713) radius 10
  arc A5 centre (-45, -13.9002) radius 3 clockwise from (-45, -16.9002) to (-48, -13.9002)
  arc A6 centre (-45, 6.0998) radius 3 clockwise from (-48, 6.0998) to (-45, 9.0998)
  circle C2 centre (31.25, -3.9002) radius 10
  point P14 (-22.0676, -10.0491)
  point P15 (1.9324, -10.0491)
  point P17 (-22.0676, 3.9509)
  horizontal L5
  vertical L6
  horizontal L7
  vertical L8
  dimension "d187" distance P14 P15 = 24
  dimension "d188" distance P14 P17 = 14
  dimension "d189" diameter C1 = 20
sketch "BORDER" plane through (0, 0, 0) normal (0, 0, 1) x axis (1, 0, 0)
  line L1 (980, 864.6415) -> (824.5514, 864.6415)
  line L2 (980, 850) -> (980, 864.6415)
  line L3 (1040, 850) -> (980, 850)
  line L4 (1040, 655.819) -> (1040, 850)
  line L5 (1040, 640) -> (1040, 655.819)
  line L6 (1120, 640) -> (1040, 640)
  line L7 (1120, 450) -> (1120, 640)
  line L8 (1180, 450) -> (1120, 450)
  line L9 (1190, 450) -> (1180, 450)
  line L10 (1190, -370) -> (1190, 450)
  line L11 (1226.1992, -370) -> (1190, -370)
  line L12 (1226.1992, -750) -> (1226.1992, -370)
  line L13 (40, -750) -> (1226.1992, -750)
  line L14 (40, -563.9778) -> (40, -750)
  line L15 (815.5386, -563.9778) -> (40, -563.9778)
  line L16 (820, 480) -> (815.5386, -563.9778)
  line L17 (840, 480) -> (820, 480)
  line L18 (840, 630) -> (840, 480)
  line L19 (817.7693, 630) -> (840, 630)
  line L20 (817.7693, 864.6415) -> (817.7693, 630)
  line L21 (824.5514, 864.6415) -> (817.7693, 864.6415)
  horizontal L1
  perpendicular L1 L2
  perpendicular L2 L3
  perpendicular L3 L4
  perpendicular L3 L5
  perpendicular L5 L6
  perpendicular L3 L7
  perpendicular L7 L8
  perpendicular L7 L9
  perpendicular L8 L10
  perpendicular L7 L11
  perpendicular L8 L12
  perpendicular L7 L13
  perpendicular L13 L14
  perpendicular L14 L15
  perpendicular L14 L17
  perpendicular L17 L18
  perpendicular L18 L19
  perpendicular L19 L20
  perpendicular L20 L21
base_feature "Base Feature2" bodies "dogboneTool"
combine "Combine1" bodies "dogboneTool"
base_feature "Base Feature2" bodies "dogboneTool"
combine "Combine1" bodies "dogboneTool"
base_feature "Base Feature2" bodies "dogboneTool"
combine "Combine1" bodies "dogboneTool"
base_feature "Base Feature2" bodies "dogboneTool"
combine "Combine1" bodies "dogboneTool"
base_feature "Base Feature2" bodies "dogboneTool"
combine "Combine1" bodies "dogboneTool"
base_feature "Base Feature2" bodies "dogboneTool"
combine "Combine1" bodies "dogboneTool"
base_feature "Base Feature2" bodies "dogboneTool"
combine "Combine1" bodies "dogboneTool"
base_feature "Base Feature2" bodies "dogboneTool"
combine "Combine1" bodies "dogboneTool"
base_feature "Base Feature2" bodies "dogboneTool"
combine "Combine1" bodies "dogboneTool"
base_feature "Base Feature2" bodies "dogboneTool"
combine "Combine1" bodies "dogboneTool"
base_feature "Base Feature2" bodies "dogboneTool"
combine "Combine1" bodies "dogboneTool"
base_feature "Base Feature2" bodies "dogboneTool"
combine "Combine1" bodies "dogboneTool"
base_feature "Base Feature2" bodies "dogboneTool"
combine "Combine1" bodies "dogboneTool"
base_feature "Base Feature2" bodies "dogboneTool"
combine "Combine1" bodies "dogboneTool"
sketch "SHOPBOT_CUT" plane through (0, 0, 0) normal (0, 0, 1) x axis (1, 0, 0)
  line L1 (-43.75, 118.79) -> (43.75, 118.79)
  line L2 (43.75, 118.79) -> (-43.75, 118.79)
  line L3 (148.79, 118.79) -> (-148.79, 118.79)
  line L4 (-148.79, 118.79) -> (148.79, 118.79)
  line L5 (35, -130) -> (-35, -130)
  line L6 (-35, -130) -> (35, -130)
  line L7 (-121.29, -130) -> (-72.29, -130)
  line L8 (-72.29, -130) -> (-121.29, -130)
  line L9 (72.29, -130) -> (121.29, -130)
  line L10 (121.29, -130) -> (72.29, -130)
  line L11 (148.79, -130) -> (-148.79, -130)
  line L12 (-148.79, -130) -> (148.79, -130)
  line L13 (72.29, -124.79) -> (121.29, -124.79)
  line L14 (121.29, -124.79) -> (72.29, -124.79)
  line L15 (121.29, -124.79) -> (72.29, -124.79)
  line L16 (72.29, -124.79) -> (121.29, -124.79)
  line L17 (-121.29, -124.79) -> (-72.29, -124.79)
  line L18 (-72.29, -124.79) -> (-121.29, -124.79)
  line L19 (-72.29, -124.79) -> (-121.29, -124.79)
  line L20 (-121.29, -124.79) -> (-72.29, -124.79)
  line L21 (-175, -115) -> (-175, 115)
  line L22 (160, -130) -> (-160, -130)
  line L23 (175, 115) -> (175, -115)
  line L24 (-160, 130) -> (160, 130)
  line L25 (10, -108.79) -> (138.79, -108.79)
  line L26 (-140.1297, -108.79) -> (-10, -108.79)
  line L27 (-153.79, 95.1297) -> (-153.79, -95.1297)
  line L28 (-10, 108.79) -> (-140.1297, 108.79)
  line L29 (140.1297, 108.79) -> (10, 108.79)
  line L30 (153.79, -93.79) -> (153.79, 95.1297)
  line L31 (148.79, -118.79) -> (-148.79, -118.79)
  line L32 (163.79, 103.79) -> (163.79, -103.79)
  line L33 (-148.79, 118.79) -> (148.79, 118.79)
  line L34 (-163.79, -103.79) -> (-163.79, 103.79)
  line L35 (-148.79, -118.79) -> (148.79, -118.79)
  line L36 (-163.79, 103.79) -> (-163.79, -103.79)
  line L37 (148.79, 118.79) -> (-148.79, 118.79)
  line L38 (163.79, -103.79) -> (163.79, 103.79)
  line L39 (160, -130) -> (-160, -130)
  line L40 (175, 115) -> (175, -115)
  line L41 (-160, 130) -> (160, 130)
  line L42 (-175, -115) -> (-175, 115)
  line L43 (148.79, -130) -> (148.79, -123.0326)
  line L44 (160, -130) -> (148.79, -130)
  line L45 (175, 115) -> (175, -115)
  line L46 (148.79, 130) -> (160, 130)
  line L47 (148.79, 123.0326) -> (148.79, 130)
  line L48 (133.79, 118.79) -> (144.5474, 118.79)
  line L49 (133.79, 108.79) -> (133.79, 118.79)
  line L50 (148.79, 108.79) -> (133.79, 108.79)
  line L51 (163.79, -93.79) -> (163.79, 93.79)
  line L52 (133.79, -108.79) -> (148.79, -108.79)
  line L53 (133.79, -118.79) -> (133.79, -108.79)
  line L54 (144.5474, -118.79) -> (133.79, -118.79)
  line L55 (-133.79, -118.79) -> (-144.5474, -118.79)
  line L56 (-133.79, -108.79) -> (-133.79, -118.79)
  line L57 (-148.79, -108.79) -> (-133.79, -108.79)
  line L58 (-163.79, 93.79) -> (-163.79, -93.79)
  line L59 (-133.79, 108.79) -> (-148.79, 108.79)
  line L60 (-133.79, 118.79) -> (-133.79, 108.79)
  line L61 (-144.5474, 118.79) -> (-133.79, 118.79)
  line L62 (-148.79, 130) -> (-148.79, 123.0326)
  line L63 (-160, 130) -> (-148.79, 130)
  line L64 (-175, -115) -> (-175, 115)
  line L65 (-148.79, -130) -> (-160, -130)
  line L66 (-148.79, -123.0326) -> (-148.79, -130)
  line L67 (-175, -115) -> (-175, 115)
  line L68 (-133.79, -118.79) -> (-144.5474, -118.79)
  line L69 (-133.79, -108.79) -> (-133.79, -118.79)
  line L70 (-148.79, -108.79) -> (-133.79, -108.79)
  line L71 (-163.79, 93.79) -> (-163.79, -93.79)
  line L72 (-133.79, 108.79) -> (-148.79, 108.79)
  line L73 (-133.79, 118.79) -> (-133.79, 108.79)
  line L74 (-144.5474, 118.79) -> (-133.79, 118.79)
  line L75 (-148.79, 130) -> (-148.79, 123.0326)
  line L76 (-160, 130) -> (-148.79, 130)
  line L77 (-175, -115) -> (-175, 115)
  line L78 (-148.79, -130) -> (-160, -130)
  line L79 (-148.79, -123.0326) -> (-148.79, -130)
  line L80 (148.79, -130) -> (148.79, -123.0326)
  line L81 (160, -130) -> (148.79, -130)
  line L82 (175, 115) -> (175, -115)
  line L83 (148.79, 130) -> (160, 130)
  line L84 (148.79, 123.0326) -> (148.79, 130)
  line L85 (133.79, 118.79) -> (144.5474, 118.79)
  line L86 (133.79, 108.79) -> (133.79, 118.79)
  line L87 (148.79, 108.79) -> (133.79, 108.79)
  line L88 (163.79, -93.79) -> (163.79, 93.79)
  line L89 (133.79, -108.79) -> (148.79, -108.79)
  line L90 (133.79, -118.79) -> (133.79, -108.79)
  line L91 (144.5474, -118.79) -> (133.79, -118.79)
  line L92 (175, 115) -> (175, -115)
  line L93 (133.79, 118.79) -> (144.5474, 118.79)
  line L94 (133.79, 108.79) -> (133.79, 118.79)
  line L95 (148.79, 108.79) -> (133.79, 108.79)
  line L96 (163.79, -93.79) -> (163.79, 93.79)
  line L97 (133.79, -108.79) -> (148.79, -108.79)
  line L98 (133.79, -118.79) -> (133.79, -108.79)
  line L99 (144.5474, -118.79) -> (133.79, -118.79)
  line L100 (148.79, -130) -> (148.79, -123.0326)
  line L101 (160, -130) -> (148.79, -130)
  line L102 (175, 115) -> (175, -115)
  line L103 (148.79, 130) -> (160, 130)
  line L104 (148.79, 123.0326) -> (148.79, 130)
  line L105 (-148.79, 130) -> (-148.79, 123.0326)
  line L106 (-160, 130) -> (-148.79, 130)
  line L107 (-175, -115) -> (-175, 115)
  line L108 (-148.79, -130) -> (-160, -130)
  line L109 (-148.79, -123.0326) -> (-148.79, -130)
  line L110 (-133.79, -118.79) -> (-144.5474, -118.79)
  line L111 (-133.79, -108.79) -> (-133.79, -118.79)
  line L112 (-148.79, -108.79) -> (-133.79, -108.79)
  line L113 (-163.79, 93.79) -> (-163.79, -93.79)
  line L114 (-133.79, 108.79) -> (-148.79, 108.79)
  line L115 (-133.79, 118.79) -> (-133.79, 108.79)
  line L116 (-144.5474, 118.79) -> (-133.79, 118.79)
  line L117 (133.79, 118.79) -> (144.5474, 118.79)
  line L118 (133.79, 108.79) -> (133.79, 118.79)
  line L119 (148.79, 108.79) -> (133.79, 108.79)
  line L120 (163.79, -93.79) -> (163.79, 93.79)
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step "Arrange4" AngleFromX 0 Priority 500 AngleFromX 0 Priority 500 originOffsetX 0 originOffsetY 0 envelopeLength 600 envelopeWidth 80 envelopeSpacing 0 grainDirection 0 objectSpacing 20 frameWidth 10 placementClearance 0
sketch "BACK_FRONT" plane through (0, 0, 0) normal (0, 0, 1) x axis (1, 0, 0)
  line L1 (255, 10) -> (25, 10)
  line L2 (258.79, 51.21) -> (258.79, 40.4526)
  line L3 (248.79, 51.21) -> (258.79, 51.21)
  line L4 (248.79, 36.21) -> (248.79, 51.21)
  line L5 (46.21, 21.21) -> (233.79, 21.21)
  line L6 (31.21, 51.21) -> (31.21, 36.21)
  line L7 (21.21, 51.21) -> (31.21, 51.21)
  line L8 (21.21, 40.4526) -> (21.21, 51.21)
  line L9 (10, 36.21) -> (16.9674, 36.21)
  line L10 (10, 25) -> (10, 36.21)
  line L11 (255, 10) -> (25, 10)
  line L12 (270, 36.21) -> (270, 25)
  line L13 (263.0326, 36.21) -> (270, 36.21)
  line L14 (538.79, 51.21) -> (538.79, 40.4526)
  line L15 (528.79, 51.21) -> (538.79, 51.21)
  line L16 (528.79, 36.21) -> (528.79, 51.21)
  line L17 (326.21, 21.21) -> (513.79, 21.21)
  line L18 (311.21, 51.21) -> (311.21, 36.21)
  line L19 (301.21, 51.21) -> (311.21, 51.21)
  line L20 (301.21, 40.4526) -> (301.21, 51.21)
  line L21 (290, 36.21) -> (296.9674, 36.21)
  line L22 (290, 25) -> (290, 36.21)
  line L23 (535, 10) -> (305, 10)
  line L24 (550, 36.21) -> (550, 25)
  line L25 (543.0326, 36.21) -> (550, 36.21)
  arc A1 centre (260.9113, 38.3313) radius 3 clockwise from (263.0326, 36.21) to (258.79, 40.4526)
  arc A2 centre (233.79, 36.21) radius 15 clockwise from (248.79, 36.21) to (233.79, 21.21)
  arc A3 centre (46.21, 36.21) radius 15 clockwise from (46.21, 21.21) to (31.21, 36.21)
  arc A4 centre (19.0887, 38.3313) radius 3 clockwise from (21.21, 40.4526) to (16.9674, 36.21)
  arc A5 centre (25, 25) radius 15 clockwise from (25, 10) to (10, 25)
  arc A6 centre (255, 25) radius 15 clockwise from (270, 25) to (255, 10)
  arc A7 centre (540.9113, 38.3313) radius 3 clockwise from (543.0326, 36.21) to (538.79, 40.4526)
  arc A8 centre (513.79, 36.21) radius 15 clockwise from (528.79, 36.21) to (513.79, 21.21)
  arc A9 centre (326.21, 36.21) radius 15 clockwise from (326.21, 21.21) to (311.21, 36.21)
  arc A10 centre (299.0887, 38.3313) radius 3 clockwise from (301.21, 40.4526) to (296.9674, 36.21)
  arc A11 centre (305, 25) radius 15 clockwise from (305, 10) to (290, 25)
  arc A12 centre (535, 25) radius 15 clockwise from (550, 25) to (535, 10)
step "Arrange5" AngleFromX 0 Priority 500 AngleFromX 0 Priority 500 originOffsetX 0 originOffsetY 0 envelopeLength 400 envelopeWidth 400 envelopeSpacing 0 grainDirection 0 objectSpacing 20 frameWidth 10 placementClearance 0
